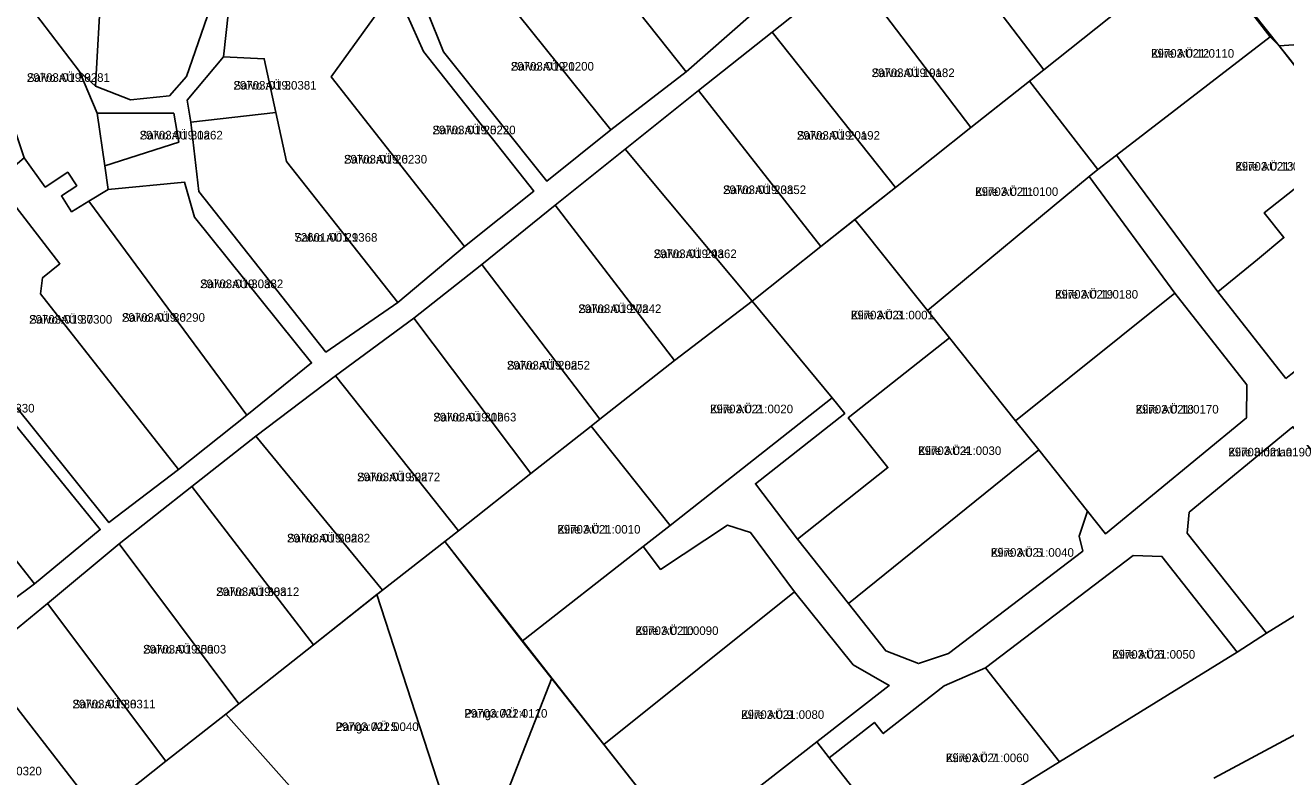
# Model space of a CAD drawing. Extents: x 504287 to 537970, y 6539941 to 6586214.
# Drawn here: x 518827.9 to 519047.9, y 6561376.7 to 6561507.8 of the extents above; entities that cross this region are included whole.
import ezdxf

# ---------------------------------------------------------------- set-up
doc = ezdxf.new("R2010")
doc.units = 0
for name, color, linetype in [('L_AADRESS', 7, 'Continuous'), ('PIIR', 7, 'Continuous'), ('TUNNUS', 7, 'Continuous')]:
    doc.layers.add(name, color=color, linetype=linetype)

msp = doc.modelspace()

# ---------------------------------------------------------------- linework, layer by layer
at = {"layer": 'PIIR'}
for points in [[(519063.55, 6561999.49), (519044.36, 6561911.82), (519029.47, 6561838.63), (519024.19, 6561806.09), (519025.66, 6561753.14), (519029.28, 6561677.28), (519056.67, 6561652.61), (519157.6, 6561519.82), (519189.87, 6561481.74), (519196.24, 6561474.66), (519184.7, 6561469.51), (519176.59, 6561469.78), (519172.41, 6561465.24), (519166.91, 6561460.45), (519158.7, 6561454.05), (519145.42, 6561444.29), (519122.8, 6561428.2), (519100.17, 6561413.07), (519078.37, 6561399.92), (519064.53, 6561392.11), (519035.37, 6561376.47)], [(519051.74, 6561579.98), (519038.15, 6561569.13), (519024.92, 6561558.89), (519011.23, 6561548.48), (518997.97, 6561538.04), (518984.81, 6561527.5), (518972.01, 6561517.52), (518958.27, 6561506.61), (518945.38, 6561496.43), (518932.62, 6561486.21), (518920.36, 6561476.4), (518907.59, 6561466.09), (518895.72, 6561456.7), (518882.05, 6561446.67), (518868.11, 6561436.13), (518856.93, 6561427.32), (518844.26, 6561417.34), (518831.75, 6561406.94), (518819.85, 6561397.13)], [(518807.6, 6561464.44), (518842.5, 6561421.05), (518854.66, 6561430.31), (518866.55, 6561439.78), (518877.87, 6561448.9), (518857.45, 6561474.31), (518855.65, 6561480.44), (518842.37, 6561479.15), (518841.8, 6561483.3), (518854.68, 6561487.42), (518853.81, 6561492.47), (518840.44, 6561492.48), (518837.33, 6561499.77), (518840.12, 6561497.16), (518846.25, 6561494.83), (518853.06, 6561495.52), (518856.02, 6561498.85), (518861.21, 6561513.86), (518848.33, 6561527.77), (518844.21, 6561533.45), (518823.85, 6561517.46)], [(519049.15, 6561437.76), (519031.05, 6561422.86), (519030.72, 6561419.19), (519044.52, 6561401.74), (519039.42, 6561398.45), (519026.29, 6561415.15), (519021.27, 6561415.32), (518995.48, 6561395.68), (518988.3, 6561392.54), (518977.63, 6561384.22), (518976.09, 6561386.18), (518968.2, 6561380.03), (518966.04, 6561382.78), (518978.68, 6561392.65), (518972.41, 6561396.21), (518962.16, 6561408.98), (518954.48, 6561419.3), (518950.46, 6561420.58), (518938.78, 6561412.88), (518935.73, 6561416.85), (518940.45, 6561420.56), (518968.73, 6561442.83), (518970.91, 6561440.09), (518955.32, 6561427.81), (518962.69, 6561418.17), (518971.58, 6561406.95), (518978.09, 6561398.65), (518983.78, 6561396.44), (518989.04, 6561398.21), (519012.49, 6561416.07), (519011.83, 6561418.67), (519013.29, 6561423.05), (519016.46, 6561419.08), (519041.03, 6561439.31), (519041.13, 6561445.07), (519028.55, 6561461.07), (519013.58, 6561481.44), (519015.08, 6561482.63), (519018.35, 6561485.15), (519036.02, 6561461.29), (519047.91, 6561446.18)], [(519035.37, 6561376.47), (519064.53, 6561392.11), (519078.37, 6561399.92), (519100.17, 6561413.07), (519122.8, 6561428.2), (519145.42, 6561444.29), (519158.7, 6561454.05), (519166.91, 6561460.45), (519172.41, 6561465.24), (519176.59, 6561469.78), (519184.69, 6561469.52), (519182.46, 6561377.54), (519190.23, 6561377.29), (519188.13, 6561345.33)], [(518981.74, 6561362.83), (519008.39, 6561379.29), (519039.42, 6561398.45), (519044.52, 6561401.74), (519066.8, 6561415.51)]]:
    msp.add_lwpolyline(points, dxfattribs=at)
for points in [[(518900.86, 6561503.17), (518918.91, 6561480.62), (518930.1, 6561489.55), (518943.23, 6561499.71), (518954.59, 6561509.61), (518933.1, 6561537.27), (518923.24, 6561553.99), (518915.7, 6561564.79), (518902.42, 6561581.1), (518892.86, 6561572.97), (518891.71, 6561560.92), (518893.09, 6561558.45), (518888.52, 6561556.77), (518885.46, 6561566.91), (518870.18, 6561554.27), (518869.73, 6561549.9), (518878.94, 6561537), (518884.7, 6561529.76), (518895.19, 6561517.4)], [(518917.09, 6561547.45), (518923.72, 6561547.43), (518923.24, 6561553.99), (518933.1, 6561537.27), (518954.59, 6561509.61), (518943.23, 6561499.71), (518916.71, 6561533.14)], [(518864.9, 6561549.53), (518849, 6561536.58), (518855.29, 6561524.41), (518862.16, 6561521.84), (518864.17, 6561517.75), (518862.47, 6561502.28), (518856.14, 6561494.73), (518856.76, 6561490.9), (518858.19, 6561478.83), (518880.36, 6561450.78), (518892.94, 6561459.44), (518904.56, 6561469.24), (518916.66, 6561478.87), (518897.38, 6561503.25), (518892.45, 6561514.35), (518886.88, 6561522.16), (518875.04, 6561537.18)], [(518894.81, 6561538.96), (518905.96, 6561538.88), (518909.58, 6561531.06), (518916.71, 6561533.14), (518943.23, 6561499.71), (518930.1, 6561489.55), (518911.73, 6561512.49), (518913.98, 6561525.62), (518903.84, 6561525.87), (518895.19, 6561517.4), (518884.7, 6561529.76)], [(518997.97, 6561538.04), (519019.3, 6561510.83), (519005.7, 6561500.05), (518984.81, 6561527.5)], [(518823.85, 6561517.46), (518844.21, 6561533.45), (518848.33, 6561527.77), (518847.4, 6561517.34), (518842.71, 6561517.67), (518841.11, 6561514.71), (518840.12, 6561497.16), (518837.33, 6561499.77)], [(519032.91, 6561521.67), (519042.16, 6561528.82), (519079.52, 6561514.53), (519085.66, 6561506.9), (519046.77, 6561504.24)], [(518840.12, 6561497.16), (518841.11, 6561514.71), (518842.71, 6561517.67), (518847.4, 6561517.34), (518848.33, 6561527.77), (518861.21, 6561513.86), (518856.02, 6561498.85), (518853.06, 6561495.52), (518846.25, 6561494.83)], [(518984.81, 6561527.5), (519005.7, 6561500.05), (518992.94, 6561489.95), (518972.01, 6561517.52)], [(518895.19, 6561517.4), (518903.84, 6561525.87), (518913.98, 6561525.62), (518911.73, 6561512.49), (518930.1, 6561489.55), (518918.91, 6561480.62), (518900.86, 6561503.17)], [(518871.6, 6561492.59), (518869.61, 6561501.97), (518862.47, 6561502.28), (518864.17, 6561517.75), (518873.95, 6561517.72), (518875.17, 6561520.27), (518885.95, 6561519.38), (518886.88, 6561522.16), (518892.45, 6561514.35), (518881.28, 6561498.84), (518904.56, 6561469.24), (518892.94, 6561459.44), (518873.51, 6561484.04)], [(519015.08, 6561482.63), (519003.17, 6561498.04), (519005.7, 6561500.05), (519019.3, 6561510.83), (519032.91, 6561521.67), (519045.19, 6561505.81), (519018.35, 6561485.15)], [(518819.51, 6561498.92), (518821.22, 6561500.31), (518813.95, 6561509.58), (518823.85, 6561517.46), (518837.33, 6561499.77), (518840.44, 6561492.48), (518841.8, 6561483.3), (518842.37, 6561479.15), (518838.96, 6561477.1), (518835.98, 6561475.27), (518834.19, 6561478.05), (518836.87, 6561479.82), (518835.31, 6561482.18), (518831.36, 6561479.57), (518827.72, 6561484.7), (518825.49, 6561491.32)], [(518972.01, 6561517.52), (518992.94, 6561489.95), (518979.76, 6561479.52), (518958.27, 6561506.61)], [(518892.45, 6561514.35), (518897.38, 6561503.25), (518916.66, 6561478.87), (518904.56, 6561469.24), (518881.28, 6561498.84)], [(518958.27, 6561506.61), (518979.76, 6561479.52), (518966.75, 6561469.19), (518945.38, 6561496.43)], [(519046.77, 6561504.24), (519085.66, 6561506.9), (519092.09, 6561498.88), (519066.96, 6561478.91)], [(519045.19, 6561505.81), (519046.77, 6561504.24), (519059.82, 6561487.46), (519044.13, 6561475.06), (519047.57, 6561470.76), (519042.99, 6561466.92), (519036.02, 6561461.29), (519018.35, 6561485.15)], [(518856.14, 6561494.73), (518862.47, 6561502.28), (518869.61, 6561501.97), (518871.6, 6561492.59), (518856.76, 6561490.9)], [(518972.71, 6561473.92), (518979.76, 6561479.52), (518992.94, 6561489.95), (519003.17, 6561498.04), (519015.08, 6561482.63), (519013.58, 6561481.44), (518985.38, 6561458.04)], [(518945.38, 6561496.43), (518966.75, 6561469.19), (518954.77, 6561459.68), (518932.62, 6561486.21)], [(518840.44, 6561492.48), (518853.81, 6561492.47), (518854.68, 6561487.42), (518841.8, 6561483.3)], [(518892.94, 6561459.44), (518880.36, 6561450.78), (518858.19, 6561478.83), (518856.76, 6561490.9), (518871.6, 6561492.59), (518873.51, 6561484.04)], [(519047.91, 6561446.18), (519036.02, 6561461.29), (519042.99, 6561466.92), (519047.57, 6561470.76), (519044.13, 6561475.06), (519059.82, 6561487.46), (519066.96, 6561478.91), (519075.44, 6561467.91), (519048.79, 6561446.87)], [(518830.9, 6561463.76), (518833.92, 6561466.2), (518825.69, 6561476.81), (518822.95, 6561480.69), (518827.72, 6561484.7), (518831.36, 6561479.57), (518835.31, 6561482.18), (518836.87, 6561479.82), (518834.19, 6561478.05), (518835.98, 6561475.27), (518838.96, 6561477.1), (518866.55, 6561439.78), (518854.66, 6561430.31), (518830.54, 6561460.94)], [(518932.62, 6561486.21), (518954.77, 6561459.68), (518941.23, 6561449.34), (518920.36, 6561476.4)], [(518780.08, 6561456.56), (518780.79, 6561467.04), (518784.96, 6561480.44), (518798.64, 6561478.35), (518804.1, 6561471.79), (518799.22, 6561467.66), (518797.87, 6561462.63), (518789.03, 6561459.51), (518798.1, 6561447.75), (518794.19, 6561444.59), (518799.84, 6561437.23), (518807.09, 6561438.74), (518829.48, 6561410.37), (518816.56, 6561400.74), (518794.5, 6561428.85), (518780.85, 6561428.25)], [(518790.96, 6561390.87), (518797.05, 6561385.16), (518816.56, 6561400.74), (518829.48, 6561410.37), (518840.97, 6561419.83), (518806.72, 6561461.96), (518797.87, 6561462.63), (518799.22, 6561467.66), (518804.1, 6561471.79), (518798.64, 6561478.35), (518784.96, 6561480.44), (518780.79, 6561467.04), (518780.08, 6561456.56), (518780.85, 6561428.25)], [(518842.37, 6561479.15), (518855.65, 6561480.44), (518857.45, 6561474.31), (518877.87, 6561448.9), (518866.55, 6561439.78), (518838.96, 6561477.1)], [(518989.2, 6561453.25), (518985.38, 6561458.04), (519013.58, 6561481.44), (519028.55, 6561461.07), (519000.74, 6561438.79)], [(518806.42, 6561473.6), (518802.46, 6561478.43), (518825.69, 6561476.81), (518833.92, 6561466.2), (518830.9, 6561463.76), (518830.54, 6561460.94), (518854.66, 6561430.31), (518842.5, 6561421.05), (518807.6, 6561464.44)], [(518920.36, 6561476.4), (518941.23, 6561449.34), (518928.2, 6561439.09), (518907.59, 6561466.09)], [(518955.32, 6561427.81), (518970.91, 6561440.09), (518968.73, 6561442.83), (518954.77, 6561459.68), (518966.75, 6561469.19), (518972.71, 6561473.92), (518985.38, 6561458.04), (518989.2, 6561453.25), (518971.54, 6561439.31), (518978.46, 6561430.64), (518962.69, 6561418.17)], [(518907.59, 6561466.09), (518928.2, 6561439.09), (518926.64, 6561437.87), (518916.15, 6561429.58), (518895.72, 6561456.7)], [(518799.84, 6561437.23), (518794.19, 6561444.59), (518798.1, 6561447.75), (518789.03, 6561459.51), (518797.87, 6561462.63), (518806.72, 6561461.96), (518840.97, 6561419.83), (518829.48, 6561410.37), (518807.09, 6561438.74)], [(519013.29, 6561423.05), (519004.79, 6561433.71), (519000.74, 6561438.79), (519028.55, 6561461.07), (519041.13, 6561445.07), (519041.03, 6561439.31), (519016.46, 6561419.08)], [(518926.64, 6561437.87), (518928.2, 6561439.09), (518941.23, 6561449.34), (518954.77, 6561459.68), (518968.73, 6561442.83), (518940.45, 6561420.56)], [(518895.72, 6561456.7), (518916.15, 6561429.58), (518903.51, 6561419.61), (518882.05, 6561446.67)], [(518962.69, 6561418.17), (518978.46, 6561430.64), (518971.54, 6561439.31), (518989.2, 6561453.25), (519000.74, 6561438.79), (519004.79, 6561433.71), (518971.58, 6561406.95)], [(518882.05, 6561446.67), (518903.51, 6561419.61), (518890.21, 6561409.23), (518868.11, 6561436.13)], [(518868.11, 6561436.13), (518890.21, 6561409.23), (518878.17, 6561399.7), (518856.93, 6561427.32)], [(518901.12, 6561417.74), (518903.51, 6561419.61), (518916.15, 6561429.58), (518926.64, 6561437.87), (518940.45, 6561420.56), (518935.73, 6561416.85), (518914.64, 6561400.38)], [(519030.72, 6561419.19), (519031.05, 6561422.86), (519049.15, 6561437.76), (519057, 6561427.87), (519066.8, 6561415.51), (519044.52, 6561401.74)], [(518983.78, 6561396.44), (518978.09, 6561398.65), (518971.58, 6561406.95), (519004.79, 6561433.71), (519013.29, 6561423.05), (519011.83, 6561418.67), (519012.49, 6561416.07), (518989.04, 6561398.21)], [(518856.93, 6561427.32), (518878.17, 6561399.7), (518865.17, 6561389.43), (518844.26, 6561417.34)], [(518914.64, 6561400.38), (518935.73, 6561416.85), (518938.78, 6561412.88), (518950.46, 6561420.58), (518954.48, 6561419.3), (518962.16, 6561408.98), (518928.87, 6561382.31)], [(518831.75, 6561406.94), (518844.26, 6561417.34), (518865.17, 6561389.43), (518862.89, 6561387.64), (518852.41, 6561379.41)], [(518896.16, 6561365.62), (518901.22, 6561371.62), (518889.25, 6561408.47), (518890.21, 6561409.23), (518901.12, 6561417.74), (518919.79, 6561393.89), (518908.6, 6561365.35), (518903.49, 6561359.42)], [(518995.48, 6561395.68), (519021.27, 6561415.32), (519026.29, 6561415.15), (519039.42, 6561398.45), (519008.39, 6561379.29)], [(518862.89, 6561387.64), (518865.17, 6561389.43), (518878.17, 6561399.7), (518889.25, 6561408.47), (518901.22, 6561371.62), (518896.16, 6561365.62), (518890.58, 6561359.18), (518880.01, 6561368.36)], [(518928.87, 6561382.31), (518962.16, 6561408.98), (518972.41, 6561396.21), (518978.68, 6561392.65), (518966.04, 6561382.78), (518942.78, 6561364.63)], [(518831.75, 6561406.94), (518852.41, 6561379.41), (518840.76, 6561370.18), (518819.85, 6561397.13)], [(518819.85, 6561397.13), (518840.76, 6561370.18), (518823.66, 6561356.76), (518796.4, 6561377.42)], [(518968.2, 6561380.03), (518976.09, 6561386.18), (518977.63, 6561384.22), (518988.3, 6561392.54), (518995.48, 6561395.68), (519008.39, 6561379.29), (518981.74, 6561362.83)], [(518915.12, 6561358.33), (518910.62, 6561353.43), (518903.49, 6561359.42), (518908.6, 6561365.35), (518919.79, 6561393.89), (518951.52, 6561353.52), (518922.04, 6561352.48)], [(518840.76, 6561370.18), (518852.41, 6561379.41), (518862.89, 6561387.64), (518880.01, 6561368.36), (518890.58, 6561359.18), (518883.56, 6561351.02), (518877.6, 6561356.17), (518830.47, 6561362.15)], [(518942.78, 6561364.63), (518966.04, 6561382.78), (518968.2, 6561380.03), (518981.74, 6561362.83), (518978.9, 6561361.08), (518960.44, 6561342.2)]]:
    msp.add_lwpolyline(points, close=True, dxfattribs=at)

# ---------------------------------------------------------------- texts
at = {"layer": 'L_AADRESS'}
for s, p in [('Kiire AÜ 12', (519024.39, 6561502.15)), ('Salvo AÜ 33', (518828.16, 6561497.94)), ('Salvo AÜ 21', (518912.64, 6561499.9)), ('Salvo AÜ 19a', (518975.61, 6561498.77)), ('Salvo AÜ 30', (518864.23, 6561496.59)), ('Salvo AÜ 31a', (518847.86, 6561487.89)), ('Salvo AÜ 25', (518898.97, 6561488.79)), ('Salvo AÜ 20a', (518962.57, 6561487.85)), ('Salvo AÜ 26', (518883.52, 6561483.69)), ('Kiire AÜ 13', (519039.09, 6561482.44)), ('Salvo AÜ 23a', (518949.68, 6561478.36)), ('Kiire AÜ 11', (518993.69, 6561478.04)), ('Salvo AÜ 29', (518874.85, 6561470.05)), ('Salvo AÜ 24a', (518937.57, 6561467.19)), ('Salvo AÜ 30a', (518858.41, 6561461.95)), ('Kiire AÜ 19', (519007.62, 6561460.12)), ('Salvo AÜ 36', (518844.75, 6561456.08)), ('Salvo AÜ 27a', (518924.41, 6561457.6)), ('Kiire AÜ 3', (518971.99, 6561456.5)), ('Salvo AÜ 37', (518828.56, 6561455.75)), ('Salvo AÜ 28a', (518911.96, 6561447.75)), ('Salvo AÜ 31b', (518899.1, 6561438.69)), ('Kiire AÜ 2', (518947.4, 6561440.12)), ('Kiire AÜ 18', (519021.69, 6561440.07)), ('Kiire AÜ 4', (518983.74, 6561432.84)), ('Kiire üldmaa', (519037.87, 6561432.59)), ('Salvo AÜ 32a', (518885.81, 6561428.26)), ('Kiire AÜ 1', (518920.76, 6561419.12)), ('Salvo AÜ 33a', (518873.57, 6561417.58)), ('Kiire AÜ 5', (518996.42, 6561415.08)), ('Salvo AÜ 38a', (518861.21, 6561408.23)), ('Kiire AÜ 10', (518934.38, 6561401.44)), ('Salvo AÜ 35a', (518848.46, 6561398.2)), ('Kiire AÜ 6', (519017.59, 6561397.3)), ('Salvo AÜ 38', (518836.13, 6561388.63)), ('Panga AÜ 4', (518904.52, 6561387.01)), ('Kiire AÜ 9', (518952.84, 6561386.8)), ('Panga AÜ 5', (518882.05, 6561384.68)), ('Kiire AÜ 7', (518988.57, 6561379.25))]:
    msp.add_text(s, height=1.5, dxfattribs=at).set_placement(p)
at = {"layer": 'TUNNUS'}
for s, p in [('29703:021:0110', (519024.39, 6561502.15)), ('29703:019:0200', (518912.64, 6561499.9)), ('29703:019:0182', (518975.61, 6561498.77)), ('29703:019:0281', (518828.16, 6561497.94)), ('29703:019:0381', (518864.23, 6561496.59)), ('29703:019:0262', (518847.86, 6561487.89)), ('29703:019:0220', (518898.97, 6561488.79)), ('29703:019:0192', (518962.57, 6561487.85)), ('29703:019:0230', (518883.52, 6561483.69)), ('29703:021:0120', (519039.09, 6561482.44)), ('29703:019:0352', (518949.68, 6561478.36)), ('29703:021:0100', (518993.69, 6561478.04)), ('72601:001:1368', (518874.85, 6561470.05)), ('29703:019:0362', (518937.57, 6561467.19)), ('29703:019:0382', (518858.41, 6561461.95)), ('29703:021:0180', (519007.62, 6561460.12)), ('29703:019:0242', (518924.41, 6561457.6)), ('29703:021:0001', (518971.99, 6561456.5)), ('29703:019:0300', (518828.56, 6561455.75)), ('29703:019:0290', (518844.75, 6561456.08)), ('29703:019:0252', (518911.96, 6561447.75)), ('29703:019:0330', (518815, 6561440.25)), ('29703:019:0263', (518899.1, 6561438.69)), ('29703:021:0020', (518947.4, 6561440.12)), ('29703:021:0170', (519021.69, 6561440.07)), ('29703:021:0030', (518983.74, 6561432.84)), ('29703:021:0190', (519037.87, 6561432.59)), ('29703:019:0272', (518885.81, 6561428.26)), ('29703:021:0010', (518920.76, 6561419.12)), ('29703:019:0282', (518873.57, 6561417.58)), ('29703:021:0040', (518996.42, 6561415.08)), ('29703:019:0312', (518861.21, 6561408.23)), ('29703:021:0090', (518934.38, 6561401.44)), ('29703:019:0003', (518848.46, 6561398.2)), ('29703:021:0050', (519017.59, 6561397.3)), ('29703:019:0311', (518836.13, 6561388.63)), ('29703:022:0110', (518904.52, 6561387.01)), ('29703:021:0080', (518952.84, 6561386.8)), ('29703:022:0040', (518882.05, 6561384.68)), ('29703:021:0060', (518988.57, 6561379.25)), ('29703:019:0320', (518816.27, 6561376.95))]:
    msp.add_text(s, height=1.5, dxfattribs=at).set_placement(p)

doc.saveas('drawing.dxf')
